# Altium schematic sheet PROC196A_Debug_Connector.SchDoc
size 431 x 279 mm; Date: Not shown in title block; ApprovedBy: Not shown in title block; CheckedBy: Not shown in title block; Author: Not shown in title block; CompanyName: Not shown in title block; Engineer: Not shown in title block; Organization: Not shown in title block; Address1: Not shown in title block; Address2: Not shown in title block; Address3: Not shown in title block; Address4: Not shown in title block; DocumentNumber: 21; Revision: Use project parameter SCH_Rev; SheetNumber: 21; SheetTotal: 25; PageSetup: Record=PageOptions¦CenterHorizontal=True¦CenterVertical=True¦PrintScale=1.00¦XCorrection=1.00¦YCorrection=1.00¦PrintKind=0¦BorderSize=5000000¦LeftOffset=0¦BottomOffset=0¦Orientation=2¦PaperLength=1000¦PaperWidth=1000¦Scale=100¦PaperSource=15¦PrintQuality=600¦MediaType=1¦DitherType=10¦PaperKind=Letter¦PrintScaleMode=1
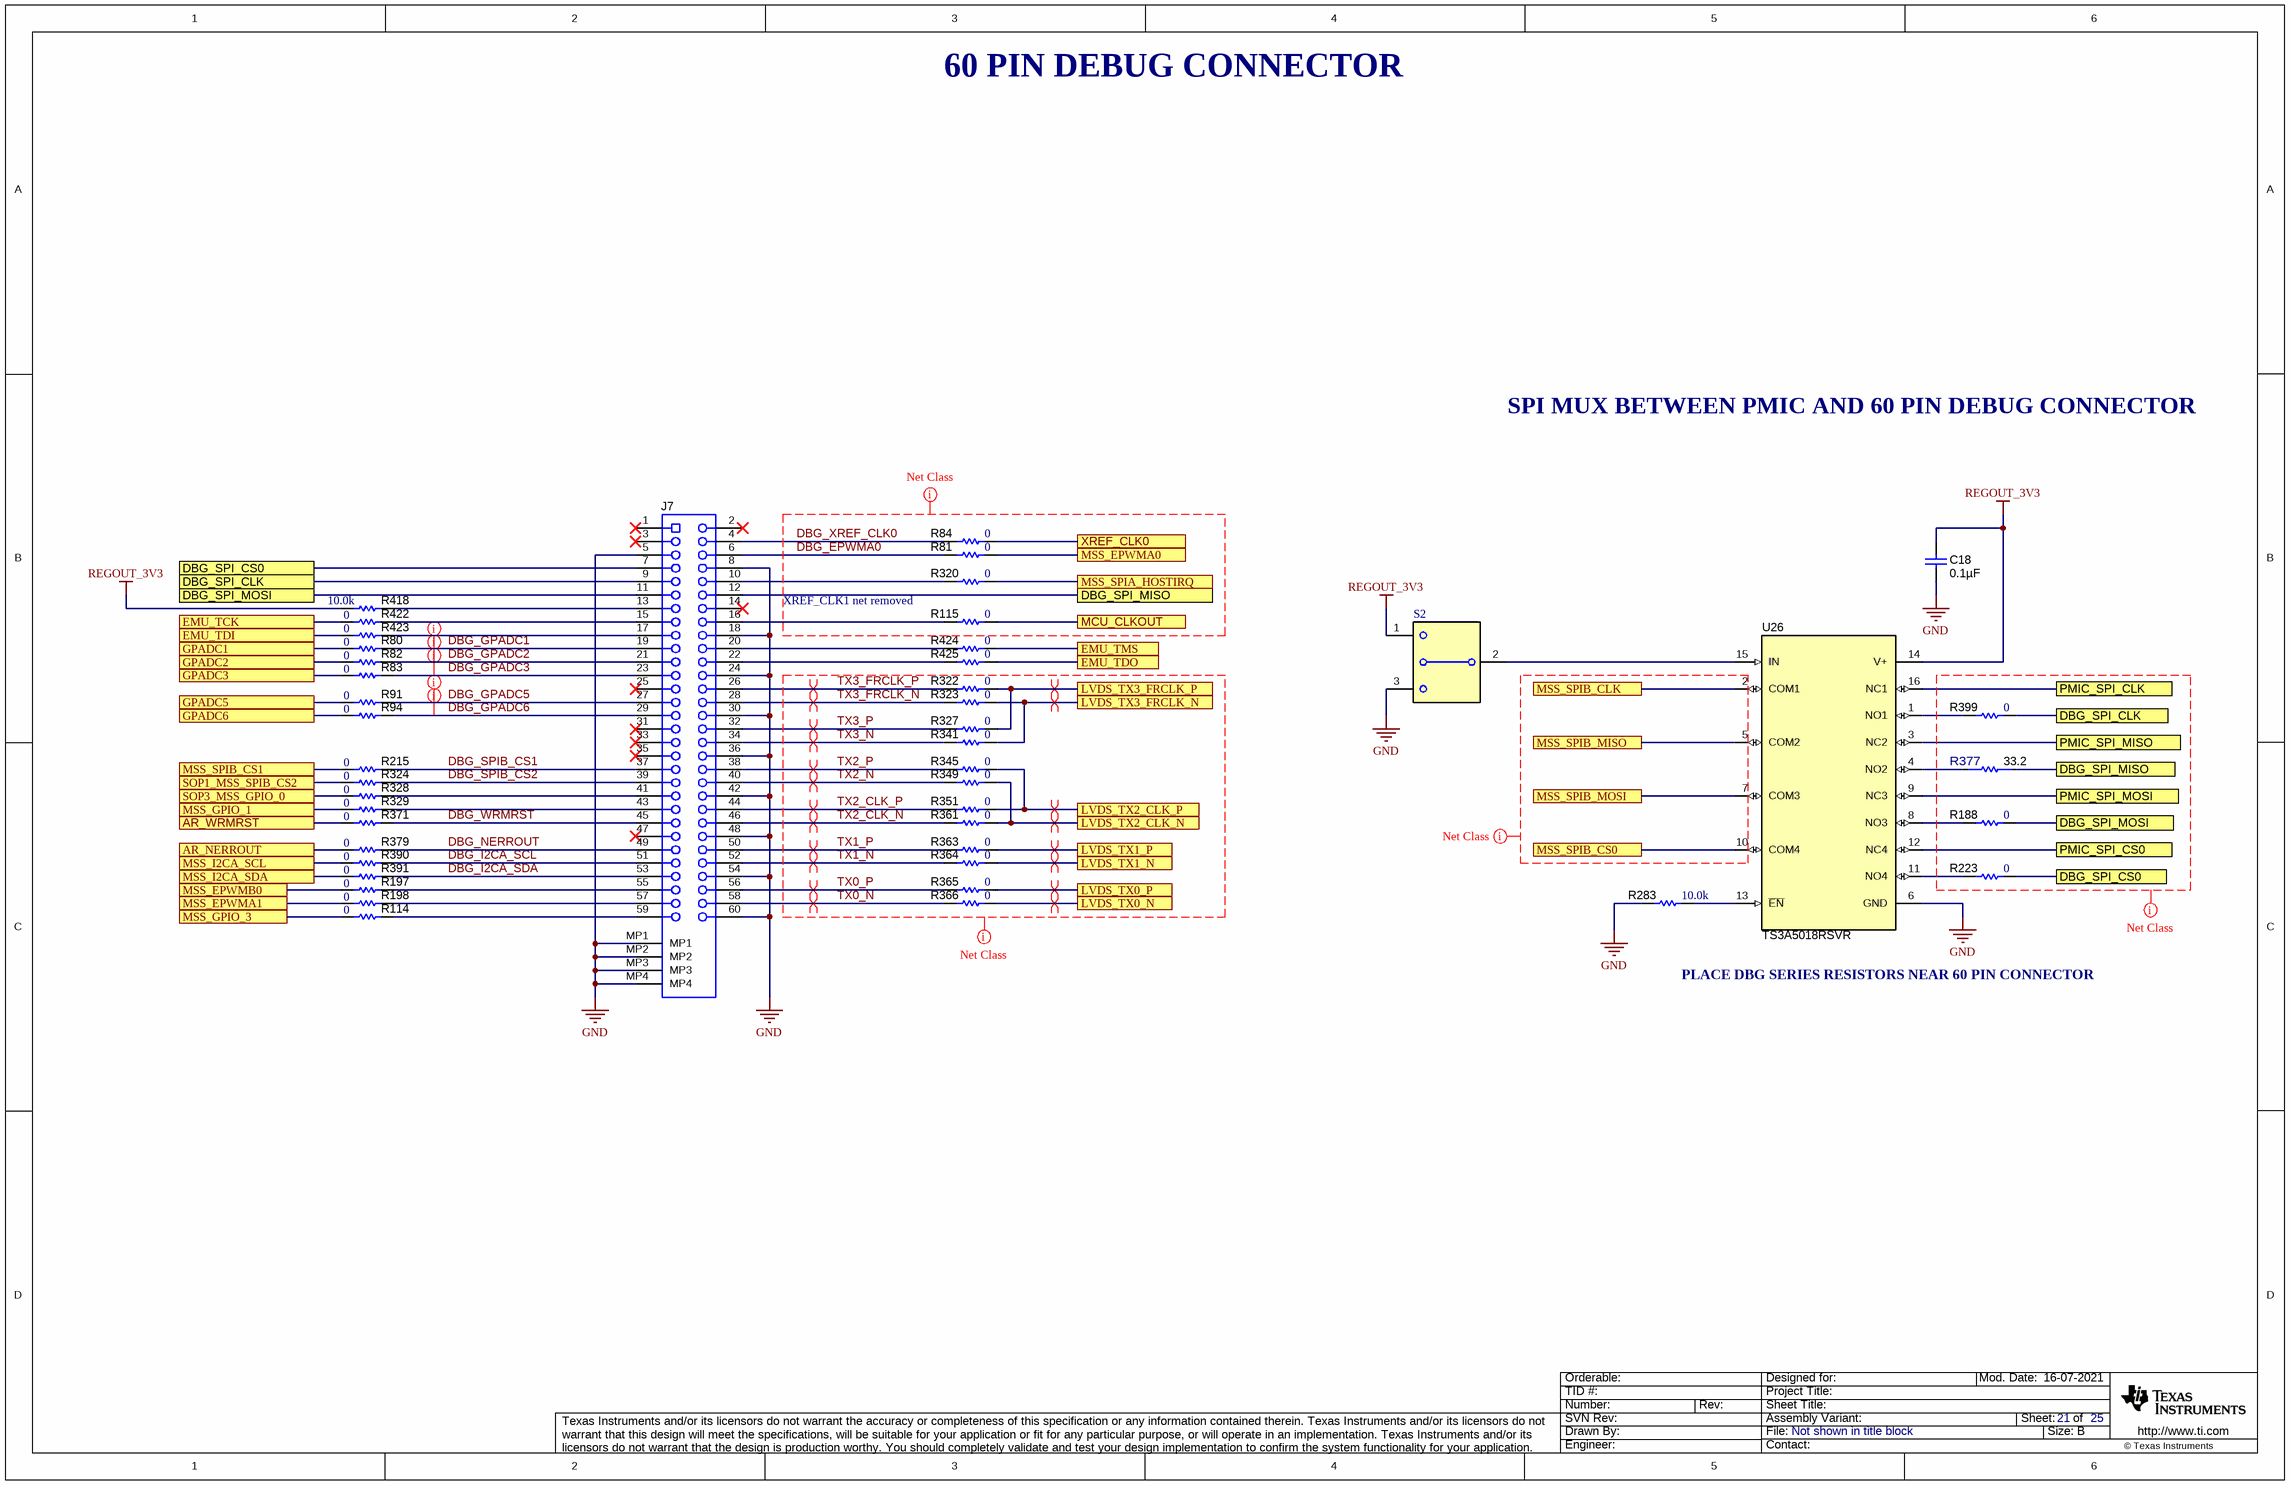
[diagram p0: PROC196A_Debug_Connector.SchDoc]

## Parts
C18  ValueDisplayed: 0.1µF  [0402L]  (hidden comment: C0402C104K8RACTU)
J7  QSH-030-01-L-D-A  [Samtec_QSH-030-01-X-D-A]  (value not drawn)
R80  ValueDisplayed: 0  [0201L]  (hidden comment: CRCW02010000Z0ED)
R81  ValueDisplayed: 0  [0201L]  (hidden comment: CRCW02010000Z0ED)
R82  ValueDisplayed: 0  [0201L]  (hidden comment: CRCW02010000Z0ED)
R83  ValueDisplayed: 0  [0201L]  (hidden comment: CRCW02010000Z0ED)
R84  ValueDisplayed: 0  [0201L]  (hidden comment: CRCW02010000Z0ED)
R91  ValueDisplayed: 0  [0201L]  (hidden comment: CRCW02010000Z0ED)
R94  ValueDisplayed: 0  [0201L]  (hidden comment: CRCW02010000Z0ED)
R114  ValueDisplayed: 0  [0201L]  (hidden comment: CRCW02010000Z0ED)
R115  ValueDisplayed: 0  [0201L]  (hidden comment: CRCW02010000Z0ED)
R188  ValueDisplayed: 0  [0201L]  (hidden comment: CRCW02010000Z0ED)
R197  ValueDisplayed: 0  [0201L]  (hidden comment: CRCW02010000Z0ED)
R198  ValueDisplayed: 0  [0201L]  (hidden comment: CRCW02010000Z0ED)
R215  ValueDisplayed: 0  [0201L]  (hidden comment: CRCW02010000Z0ED)
R223  ValueDisplayed: 0  [0201L]  (hidden comment: CRCW02010000Z0ED)
R283  ValueDisplayed: 10.0k  [0402L]  (hidden comment: CRCW040210K0FKED)
R320  ValueDisplayed: 0  [0201L]  (hidden comment: CRCW02010000Z0ED)
R322  ValueDisplayed: 0  [0201L]  (hidden comment: CRCW02010000Z0ED)
R323  ValueDisplayed: 0  [0201L]  (hidden comment: CRCW02010000Z0ED)
R324  ValueDisplayed: 0  [0201L]  (hidden comment: CRCW02010000Z0ED)
R327  ValueDisplayed: 0  [0201L]  (hidden comment: CRCW02010000Z0ED)
R328  ValueDisplayed: 0  [0201L]  (hidden comment: CRCW02010000Z0ED)
R329  ValueDisplayed: 0  [0201L]  (hidden comment: CRCW02010000Z0ED)
R341  ValueDisplayed: 0  [0201L]  (hidden comment: CRCW02010000Z0ED)
R345  ValueDisplayed: 0  [0201L]  (hidden comment: CRCW02010000Z0ED)
R349  ValueDisplayed: 0  [0201L]  (hidden comment: CRCW02010000Z0ED)
R351  ValueDisplayed: 0  [0201L]  (hidden comment: CRCW02010000Z0ED)
R361  ValueDisplayed: 0  [0201L]  (hidden comment: CRCW02010000Z0ED)
R363  ValueDisplayed: 0  [0201L]  (hidden comment: CRCW02010000Z0ED)
R364  ValueDisplayed: 0  [0201L]  (hidden comment: CRCW02010000Z0ED)
R365  ValueDisplayed: 0  [0201L]  (hidden comment: CRCW02010000Z0ED)
R366  ValueDisplayed: 0  [0201L]  (hidden comment: CRCW02010000Z0ED)
R371  ValueDisplayed: 0  [0201L]  (hidden comment: CRCW02010000Z0ED)
R377  Res_ohm: 33.2  [FP-ERJ-1GNF33R2C_0201-MFG]  (hidden comment: ERJ-1GNF33R2C)
R379  ValueDisplayed: 0  [0201L]  (hidden comment: CRCW02010000Z0ED)
R390  ValueDisplayed: 0  [0201L]  (hidden comment: CRCW02010000Z0ED)
R391  ValueDisplayed: 0  [0201L]  (hidden comment: CRCW02010000Z0ED)
R399  ValueDisplayed: 0  [0201L]  (hidden comment: CRCW02010000Z0ED)
R418  ValueDisplayed: 10.0k  [0402L]  (hidden comment: CRCW040210K0FKED)
R422  ValueDisplayed: 0  [0201L]  (hidden comment: CRCW02010000Z0ED)
R423  ValueDisplayed: 0  [0201L]  (hidden comment: CRCW02010000Z0ED)
R424  ValueDisplayed: 0  [0201L]  (hidden comment: CRCW02010000Z0ED)
R425  ValueDisplayed: 0  [0201L]  (hidden comment: CRCW02010000Z0ED)
S2  CJS-1201TA  [SW_CJS_1201A]  (value not drawn)
U26  TS3A5018RSVR  [RSV0016A]

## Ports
AR_NERROUT, AR_WRMRST, DBG_SPI_CLK, DBG_SPI_CS0, DBG_SPI_MISO, DBG_SPI_MOSI, EMU_TCK, EMU_TDI, EMU_TDO, EMU_TMS, GPADC1, GPADC2, GPADC3, GPADC5, GPADC6, LVDS_TX0_N, LVDS_TX0_P, LVDS_TX1_N, LVDS_TX1_P, LVDS_TX2_CLK_N, LVDS_TX2_CLK_P, LVDS_TX3_FRCLK_N, LVDS_TX3_FRCLK_P, MCU_CLKOUT, MSS_EPWMA0, MSS_EPWMA1, MSS_EPWMB0, MSS_GPIO_1, MSS_GPIO_3, MSS_I2CA_SCL, MSS_I2CA_SDA, MSS_SPIA_HOSTIRQ, MSS_SPIB_CLK, MSS_SPIB_CS0, MSS_SPIB_CS1, MSS_SPIB_MISO, MSS_SPIB_MOSI, PMIC_SPI_CLK, PMIC_SPI_CS0, PMIC_SPI_MISO, PMIC_SPI_MOSI, SOP1_MSS_SPIB_CS2, SOP3_MSS_GPIO_0, XREF_CLK0

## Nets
GND: C18.1 J7.5 J7.8 J7.18 J7.24 J7.30 J7.36 J7.42 J7.48 J7.54 J7.60 J7.MP1 J7.MP2 J7.MP3 J7.MP4 R283.2 S2.3 U26.6(GND)
REGOUT_3V3: C18.2 R418.2 S2.1 U26.14(V+)
AR_NERROUT: R379.1 ; port AR_NERROUT
AR_WRMRST: R371.1 ; port AR_WRMRST
DBG_EPWMA0: J7.6 R81.2
DBG_GPADC1: J7.19 R80.2
DBG_GPADC2: J7.21 R82.2
DBG_GPADC3: J7.23 R83.2
DBG_GPADC5: J7.27 R91.2
DBG_GPADC6: J7.29 R94.2
DBG_I2CA_SCL: J7.51 R390.2
DBG_I2CA_SDA: J7.53 R391.2
DBG_NERROUT: J7.49 R379.2
DBG_SPI_CLK: J7.9 R399.2 ; port DBG_SPI_CLK
DBG_SPI_CS0: J7.7 R223.2 ; port DBG_SPI_CS0
DBG_SPI_MISO: J7.12 R377.1 ; port DBG_SPI_MISO
DBG_SPI_MOSI: J7.11 R188.2 ; port DBG_SPI_MOSI
DBG_SPIB_CS1: J7.37 R215.2
DBG_SPIB_CS2: J7.39 R324.2
DBG_WRMRST: J7.45 R371.2
DBG_XREF_CLK0: J7.4 R84.2
EMU_TCK: R422.1 ; port EMU_TCK
EMU_TDI: R423.1 ; port EMU_TDI
EMU_TDO: R425.2 ; port EMU_TDO
EMU_TMS: R424.2 ; port EMU_TMS
GPADC1: R80.1 ; port GPADC1
GPADC2: R82.1 ; port GPADC2
GPADC3: R83.1 ; port GPADC3
GPADC5: R91.1 ; port GPADC5
GPADC6: R94.1 ; port GPADC6
LVDS_TX0_N: R366.2 ; port LVDS_TX0_N
LVDS_TX0_P: R365.2 ; port LVDS_TX0_P
LVDS_TX1_N: R364.2 ; port LVDS_TX1_N
LVDS_TX1_P: R363.2 ; port LVDS_TX1_P
LVDS_TX2_CLK_N: R349.2 R361.2 ; port LVDS_TX2_CLK_N
LVDS_TX2_CLK_P: R345.2 R351.2 ; port LVDS_TX2_CLK_P
LVDS_TX3_FRCLK_N: R323.2 R341.2 ; port LVDS_TX3_FRCLK_N
LVDS_TX3_FRCLK_P: R322.2 R327.2 ; port LVDS_TX3_FRCLK_P
MCU_CLKOUT: R115.1 ; port MCU_CLKOUT
MSS_EPWMA0: R81.1 ; port MSS_EPWMA0
MSS_EPWMA1: R198.1 ; port MSS_EPWMA1
MSS_EPWMB0: R197.1 ; port MSS_EPWMB0
MSS_GPIO_1: R329.1 ; port MSS_GPIO_1
MSS_GPIO_3: R114.1 ; port MSS_GPIO_3
MSS_I2CA_SCL: R390.1 ; port MSS_I2CA_SCL
MSS_I2CA_SDA: R391.1 ; port MSS_I2CA_SDA
MSS_SPIA_HOSTIRQ: R320.1 ; port MSS_SPIA_HOSTIRQ
MSS_SPIB_CLK: U26.2(COM1) ; port MSS_SPIB_CLK
MSS_SPIB_CS0: U26.10(COM4) ; port MSS_SPIB_CS0
MSS_SPIB_CS1: R215.1 ; port MSS_SPIB_CS1
MSS_SPIB_MISO: U26.5(COM2) ; port MSS_SPIB_MISO
MSS_SPIB_MOSI: U26.7(COM3) ; port MSS_SPIB_MOSI
PMIC_SPI_CLK: U26.16(NC1) ; port PMIC_SPI_CLK
PMIC_SPI_CS0: U26.12(NC4) ; port PMIC_SPI_CS0
PMIC_SPI_MISO: U26.3(NC2) ; port PMIC_SPI_MISO
PMIC_SPI_MOSI: U26.9(NC3) ; port PMIC_SPI_MOSI
SOP1_MSS_SPIB_CS2: R324.1 ; port SOP1_MSS_SPIB_CS2
SOP3_MSS_GPIO_0: R328.1 ; port SOP3_MSS_GPIO_0
TX0_N: J7.58 R366.1
TX0_P: J7.56 R365.1
TX1_N: J7.52 R364.1
TX1_P: J7.50 R363.1
TX2_CLK_N: J7.46 R361.1
TX2_CLK_P: J7.44 R351.1
TX2_N: J7.40 R349.1
TX2_P: J7.38 R345.1
TX3_FRCLK_N: J7.28 R323.1
TX3_FRCLK_P: J7.26 R322.1
TX3_N: J7.34 R341.1
TX3_P: J7.32 R327.1
XREF_CLK0: R84.1 ; port XREF_CLK0
NetJ7_10: J7.10 R320.2
NetJ7_13: J7.13 R418.1
NetJ7_15: J7.15 R422.2
NetJ7_16: J7.16 R115.2
NetJ7_17: J7.17 R423.2
NetJ7_20: J7.20 R424.1
NetJ7_22: J7.22 R425.1
NetJ7_41: J7.41 R328.2
NetJ7_43: J7.43 R329.2
NetJ7_55: J7.55 R197.2
NetJ7_57: J7.57 R198.2
NetJ7_59: J7.59 R114.2
NetR188_1: R188.1 U26.8(NO3)
NetR223_1: R223.1 U26.11(NO4)
NetR283_1: R283.1 U26.13(~{EN})
NetR377_2: R377.2 U26.4(NO2)
NetR399_1: R399.1 U26.1(NO1)
NetS2_2: S2.2(COM) U26.15(IN)

Not connected (* = marked no-connect by the designer): J7 1* 2* 3* 14* 25* 31* 33* 35* 47*

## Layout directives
net class LVDS: TX0_N, TX0_P, TX1_N, TX1_P, TX2_CLK_N, TX2_CLK_P, TX2_N, TX2_P, TX3_FRCLK_N, TX3_FRCLK_P, TX3_N, TX3_P
net class CLKOUT: DBG_EPWMA0, DBG_XREF_CLK0
net class JTAG: (no net found under the mark)
net class GPADC: DBG_GPADC1, DBG_GPADC2, DBG_GPADC3, DBG_GPADC5, DBG_GPADC6
differential pair: LVDS_TX0_N, LVDS_TX0_P, LVDS_TX1_N, LVDS_TX1_P, LVDS_TX2_CLK_N, LVDS_TX2_CLK_P, LVDS_TX3_FRCLK_N, LVDS_TX3_FRCLK_P, TX0_N, TX0_P, TX1_N, TX1_P, TX2_CLK_N, TX2_CLK_P, TX2_N, TX2_P, TX3_FRCLK_N, TX3_FRCLK_P, TX3_N, TX3_P

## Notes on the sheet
- 60 PIN DEBUG CONNECTOR
- SPI MUX BETWEEN PMIC AND 60 PIN DEBUG CONNECTOR
- XREF_CLK1 net removed
- PLACE DBG SERIES RESISTORS NEAR 60 PIN CONNECTOR

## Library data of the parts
C18 = CMP-0078241-1: CAP, CERM, 0.1 µF, 10 V,+/- 10%, X7R, 0402; Manufacturer: Kemet; TaMin_C: -55°C; Polarized: N; SizeAreaWB_mm2: 3; U/M: EA; Value: 0.1uF; TaMax_C: 125°C; SizeZ_mm: 0.6; SizeX_mm: 1; SizeY_mm: 0.5; Cap_Case: 0402; Value2: 10V; Cap_F: 100nF; AEC Category: Q200
J7 = CMP-0075524-1: Receptacle, 0.5 mm, 30x2, Gold, TH; Manufacturer: Samtec; Pitch_mm: 0.5; Gender: Female; Green_REACh: Passed; CT: False; Shrouded: N; RowSpacing_mm: 5.73; Green_Lifecycle: Active; Row_Count: 2
R80-R84 R91 R94 R114 R115 R188 R197 R198 R215 R223 R320 R322-R324 R327-R329 R341 R345 R349 R351 R361 R363-R366 R371 R379 R390 R391 R399 R422-R425 = CMP-0027008-4: RES, 0, 5%, 0.05 W, 0201; Manufacturer: Vishay-Dale; Power_W: 50mW; TempCo: ppm/C; Value_Code: 0000; Value: 0; EIA_Code: E24; SizeX_mm: 0.6; SizeY_mm: 0.3; SizeZ_mm: 0.26; Value2: 0.05W; SizeArea_mm2: 0.18; AEC Qualified: N; AEC Category: Q200
R283 R418 = CMP-0025958-3: RES, 10.0 k, 1%, 0.063 W, AEC-Q200 Grade 0, 0402; Manufacturer: Vishay-Dale; Power_W: 63mW; TempCo: 100 ppm/C; Value_Code: 10k0; Value: 10.0k; EIA_Code: E96; Res_ohm: 10k; SizeX_mm: 1; SizeY_mm: 0.5; SizeZ_mm: 0.6; Value2: 0.063W; AEC Qualified: Y; VDC_V: 50V; AEC Category: Q200; AEC Grade: 0
R377 = CMP-0089575-2: Res Thick Film 0201 33.2 Ohm 1% 0.05W(1/20W) ±200ppm/C Pad SMD Automotive T/R; Manufacturer: Panasonic; TempCo: 200ppm/°C; VDC_V: 25V; AEC Qualified: Yes; SizeZ_mm: 0.26mm; Power_W: 50mW; AEC Grade: Grade 1; Value: 33.2
S2 = CMP-0002159-2: Slide SW, SPDT 0.1A 50VDC; Manufacturer: Copal Electronics; CurrentRating_mA: 100A; SwitchFunction: On-Off-On; VDC_V: 50V; PositionCount: 1; CompType: Switch
U26 = CMP-0067415-1: 10-Ohm Quad SPDT Analog Switch, RSV0016A (UQFN-16); Alternate Manufacturer: Texas Instruments; SizeAreaWB_mm2: 10.08; U/M: EA; SizeZ_mm: 0.55; SizeX_mm: 1.8; SizeY_mm: 2.6; SizeArea_mm2: 4.68; CompType: IC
